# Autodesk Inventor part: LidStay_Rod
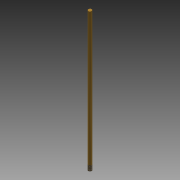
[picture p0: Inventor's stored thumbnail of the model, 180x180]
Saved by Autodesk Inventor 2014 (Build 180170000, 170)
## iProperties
Created: 2014-03
Part Number: LidStay_Rod
Material: Brass, Soft Yellow
Document SubType Name: Modeling
Designer: Beast
Density: 8.47 g/cm^3
Appearance: Brass - Satin
Author: Beast
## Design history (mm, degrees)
sketch "Sketch1"
  geometry: C1 r 3.175 at (0, 0); 1 further point
  constraints: 1 centre point, 1 coincident
  dimensions: "d0" = 6.35 diameter of C1
extrude "Extrusion1" new body sketch "Sketch1" distance "d1" = 254; taper "d2" = 0 deg
chamfer "Chamfer1" distance "d3" = 0.254; stored, may be unused: second distance "d4" = 3.175, angle "d5" = 45 deg
thread "Thread1" dims "d6" = 9.525, "d7" = 0
body "Solid1"
